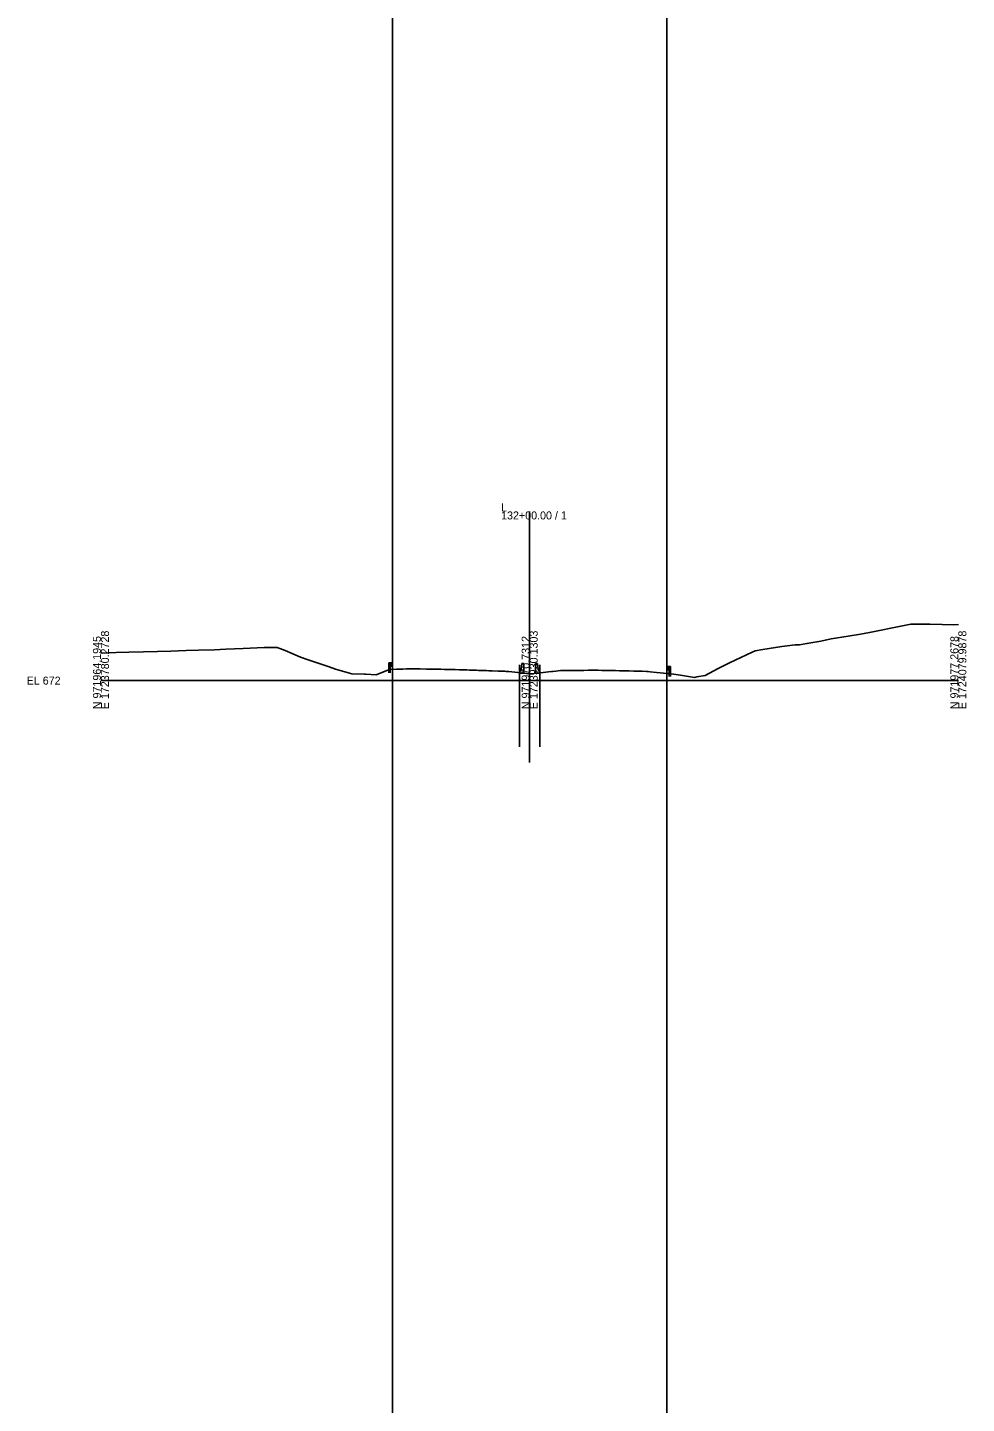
# Model space of a CAD drawing. Extents: x -26 to 303, y -29 to 15026.
# Drawn here: x -25.7 to 302.8, y 9247 to 9728.6 of the extents above; entities that cross this region are included whole.
import ezdxf

# ---------------------------------------------------------------- set-up
doc = ezdxf.new("R2010")
doc.units = 0
for name, color, linetype in [('Exist Cross Section Cell', 7, 'Continuous'), ('Exist XS Center Line Elevation Label', 7, 'Continuous'), ('Exist XS Ground Line', 7, 'Continuous'), ('Scratch_Level_0', 7, 'Continuous'), ('Typical Guardrail CELL', 7, 'Continuous'), ('Typical Median Barrier CELL', 7, 'Continuous')]:
    doc.layers.add(name, color=color, linetype=linetype)

msp = doc.modelspace()

# ---------------------------------------------------------------- linework, layer by layer
at = {"layer": 'Exist Cross Section Cell'}
for p, q in [((150, 9500), (150, 9559.21)), ((0, 9500), (150, 9500)), ((150, 9500), (300, 9500))]:
    msp.add_line(p, q, dxfattribs=at)
at = {"layer": 'Exist XS Ground Line'}
msp.add_lwpolyline([(0, 9509.62), (5.32, 9509.79), (9.75, 9509.94), (14.91, 9510.09), (19.76, 9510.22), (24.5, 9510.34), (29.77, 9510.54), (34.09, 9510.63), (39.78, 9510.78), (43.68, 9511.04), (49.79, 9511.27), (57.07, 9511.61), (61.61, 9511.63), (64.46, 9510.54), (69.8, 9508.22), (72.45, 9507.24), (79.81, 9504.79), (82.09, 9504.05), (87.81, 9502.33), (92.18, 9502.27), (92.71, 9502.27), (96.25, 9502.06), (96.57, 9502.14), (100.96, 9503.88), (103.45, 9504), (104.01, 9504.01), (104.7, 9504.04), (105.67, 9504.06), (106.92, 9504.1), (107.39, 9504.1), (108.96, 9504.1), (111.36, 9504.09), (111.68, 9504.08), (113.95, 9504.03), (115.01, 9504.02), (116.45, 9504), (117.63, 9503.98), (118.95, 9503.95), (120.16, 9503.92), (121.44, 9503.88), (122.41, 9503.87), (123.08, 9503.86), (123.48, 9503.85), (123.93, 9503.84), (125.44, 9503.79), (126.43, 9503.76), (128.06, 9503.72), (128.92, 9503.7), (129.7, 9503.68), (131.44, 9503.62), (132.11, 9503.59), (133.95, 9503.52), (134.93, 9503.48), (135.7, 9503.46), (136.09, 9503.44), (136.47, 9503.42), (136.94, 9503.4), (138.96, 9503.35), (141.26, 9503.27), (141.74, 9503.23), (142.7, 9503.13), (150, 9502.41), (150.43, 9502.37), (153.77, 9502.7), (156.58, 9503.06), (157.66, 9503.19), (158.16, 9503.24), (159.17, 9503.34), (160.77, 9503.5), (161.54, 9503.52), (163.35, 9503.55), (164.25, 9503.57), (165.73, 9503.57), (166.49, 9503.57), (167.34, 9503.58), (168.98, 9503.59), (170.52, 9503.6), (171.5, 9503.6), (172.57, 9503.6), (174, 9503.6), (175.31, 9503.59), (176.51, 9503.59), (177.12, 9503.58), (177.6, 9503.57), (178.99, 9503.53), (180.08, 9503.5), (181.48, 9503.47), (183.02, 9503.43), (183.97, 9503.41), (184.86, 9503.38), (186.49, 9503.33), (188.25, 9503.28), (189.34, 9503.25), (190.88, 9503.18), (191.42, 9503.16), (192.22, 9503.1), (194.42, 9502.89), (198.13, 9502.53), (198.64, 9502.48), (199.53, 9502.38), (202.82, 9501.9), (207.7, 9501.1), (208.48, 9501.3), (211.41, 9501.8), (215.98, 9504.26), (219.94, 9506.25), (227.88, 9509.91), (228.9, 9510.37), (231.63, 9510.94), (238.25, 9511.97), (242.9, 9512.52), (244.39, 9512.52), (246.99, 9512.96), (251.88, 9513.84), (255.55, 9514.67), (261.47, 9515.51), (265.76, 9516.21), (268.9, 9516.82), (272.94, 9517.63), (276.41, 9518.38), (283.36, 9519.7), (288.25, 9519.74), (290.02, 9519.7), (294.3, 9519.63), (298.4, 9519.56), (300, 9519.58)], dxfattribs=at)
at = {"layer": 'Scratch_Level_0'}
for p, q in [((102, 15009.56), (102, -28.7)), ((198, 15009.56), (198, -28.7)), ((146.46, 9505.5), (146.46, 9476.8)), ((153.54, 9505.5), (153.54, 9476.8)), ((150, 9500), (150, 9471.3)), ((150, 9500), (150, 9471.3))]:
    msp.add_line(p, q, dxfattribs=at)
at = {"layer": 'Typical Guardrail CELL'}
for p, q in [((101.18, 9506.25), (100.68, 9506.25)), ((100.68, 9506.25), (100.68, 9503.77)), ((101.18, 9506.25), (101.18, 9503.77)), ((101.18, 9506.25), (101.68, 9506.25)), ((101.68, 9506.25), (101.68, 9505.09)), ((101.68, 9506.25), (101.97, 9506.05)), ((101.18, 9503.77), (100.68, 9503.77)), ((100.68, 9503.77), (100.68, 9502.76)), ((101.18, 9505.09), (101.68, 9505.09)), ((101.18, 9503.77), (101.18, 9502.76)), ((101.68, 9505.72), (101.97, 9505.92)), ((101.68, 9505.67), (101.68, 9505.72)), ((101.68, 9505.67), (101.68, 9505.63)), ((101.68, 9505.63), (101.97, 9505.42)), ((101.68, 9505.09), (101.97, 9505.29)), ((198.32, 9504.89), (198.03, 9504.69)), ((198.32, 9504.36), (198.03, 9504.56)), ((198.32, 9504.26), (198.03, 9504.06)), ((198.32, 9503.73), (198.03, 9503.93)), ((198.82, 9504.89), (198.32, 9504.89)), ((198.32, 9504.89), (198.32, 9503.73)), ((198.32, 9504.31), (198.32, 9504.36)), ((198.32, 9504.31), (198.32, 9504.26)), ((198.82, 9503.73), (198.32, 9503.73)), ((198.82, 9504.89), (198.82, 9502.4)), ((198.82, 9504.89), (199.32, 9504.89)), ((198.82, 9502.4), (199.32, 9502.4)), ((198.82, 9502.4), (198.82, 9501.39)), ((199.32, 9504.89), (199.32, 9502.4)), ((199.32, 9502.4), (199.32, 9501.39))]:
    msp.add_line(p, q, dxfattribs=at)
for centre, start, end in [((101.92, 9505.98), 304.9888, 54.997), ((101.92, 9505.36), 304.9634, 54.9941), ((198.08, 9504.62), 125.003, 235.0112), ((198.08, 9504), 125.0059, 235.0366)]:
    msp.add_arc(centre, 0.0776, start, end, dxfattribs=at)
at = {"layer": 'Typical Median Barrier CELL'}
for p, q in [((146.46, 9502.97), (146.92, 9503.63)), ((146.46, 9502.55), (146.46, 9502.97)), ((147.96, 9502.55), (146.46, 9502.55)), ((147.07, 9504.02), (147.29, 9505.97)), ((147.29, 9505.97), (147.96, 9505.97)), ((147.96, 9505.97), (147.96, 9502.55)), ((152.71, 9505.97), (152.04, 9505.97)), ((152.04, 9505.97), (152.04, 9502.55)), ((152.04, 9502.55), (153.54, 9502.55)), ((152.93, 9504.02), (152.71, 9505.97)), ((153.54, 9502.97), (153.08, 9503.63)), ((153.54, 9502.55), (153.54, 9502.97))]:
    msp.add_line(p, q, dxfattribs=at)
for centre, start, end in [((146.24, 9504.1), 325.0039, 353.9447), ((153.76, 9504.1), 186.0553, 214.9961)]:
    msp.add_arc(centre, 0.833, start, end, dxfattribs=at)

# ---------------------------------------------------------------- texts
at = {"layer": 'Exist Cross Section Cell'}
for s, p in [('132+00.00 / 1', (140, 9556.41)), ('L', (140, 9559.21)), ('EL 672', (-26, 9498.6))]:
    msp.add_text(s, height=2.8, dxfattribs=at).set_placement(p)
for s, p in [('E 1723780.2728', (2.8, 9490)), ('E 1723930.1303', (152.8, 9490)), ('E 1724079.9878', (302.8, 9490)), ('N 971964.1945', (0, 9490)), ('N 971970.7312', (150, 9490)), ('N 971977.2678', (300, 9490))]:
    msp.add_text(s, height=2.8, rotation=90, dxfattribs=at).set_placement(p)
at = {"layer": 'Exist XS Center Line Elevation Label'}
msp.add_text('674.41', height=0.18, dxfattribs=at).set_placement((149.65, 9501.92))

doc.saveas('drawing.dxf')
